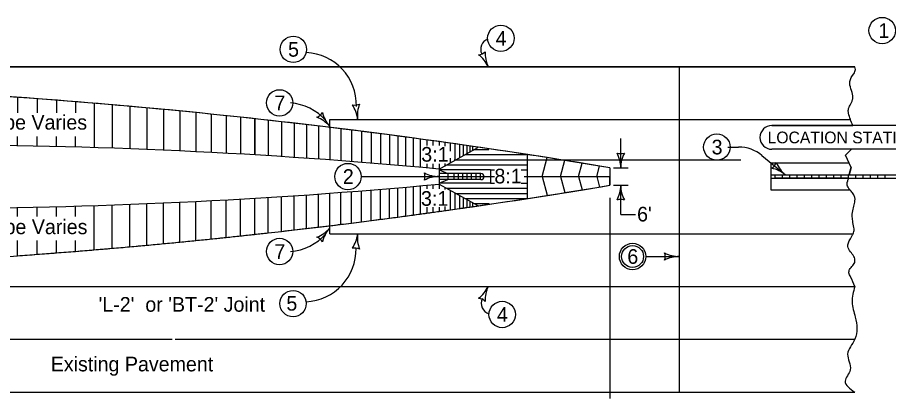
# Model space of a CAD drawing. Extents: x 10028 to 81668, y 3581 to 11018.
# Drawn here: x 14614 to 15802, y 4220 to 4740 of the extents above; entities that cross this region are included whole.
import ezdxf

# ---------------------------------------------------------------- set-up
doc = ezdxf.new("R2010")
doc.units = 0
for name, color, linetype in [('dsnCellsNorthArrow', 7, 'Continuous'), ('dsnStdLabel', 7, 'Continuous'), ('dsnStdShading', 7, 'Continuous'), ('dsnTextFinalPlan', 7, 'Continuous'), ('dsnTextTabulation', 7, 'Continuous'), ('Level 10', 7, 'Continuous'), ('Level 5', 7, 'Continuous'), ('Level 6', 7, 'Continuous'), ('SheetAddendum', 7, 'Continuous')]:
    doc.layers.add(name, color=color, linetype=linetype)

msp = doc.modelspace()

# ---------------------------------------------------------------- linework, layer by layer
at = {"layer": 'dsnCellsNorthArrow'}
for p, q in [((13916.5, 4301.1), (14824.8, 4301.1)), ((14828.9, 4301.1), (15755.5, 4301.1))]:
    msp.add_line(p, q, dxfattribs=at)
at = {"layer": 'dsnStdLabel'}
for p, q in [((15849.9, 4592.8), (15642.4, 4592.8)), ((15849.9, 4560.3), (15642.3, 4560.3))]:
    msp.add_line(p, q, dxfattribs=at)
msp.add_arc((15642.4, 4576.5), 16.2, 90, 270, dxfattribs=at)
at = {"layer": 'dsnStdShading'}
for p, q in [((15516.2, 4672.7), (13978.9, 4672.7)), ((15755.4, 4672.7), (15516.2, 4672.7)), ((14973.8, 4597.9), (14973.8, 4597.9)), ((15642.4, 4592.8), (15752.9, 4592.8)), ((15751.1, 4560.3), (15642.4, 4560.3)), ((15742.6, 4552.1), (15751.1, 4560.3)), ((15336.2, 4548.9), (15336.2, 4549)), ((15750.4, 4535.4), (15742.6, 4552.1)), ((15421.4, 4535.1), (15421.4, 4523.1)), ((15646.9, 4520.7), (15646.9, 4525.5)), ((15421.4, 4523.1), (15421.4, 4511.1)), ((15203.8, 4477.5), (15203.8, 4477.5)), ((15216.4, 4479.3), (15216.4, 4479.3)), ((15221.8, 4480.1), (15221.8, 4480.1)), ((15226.6, 4480.8), (15226.6, 4480.8)), ((15230.8, 4481.4), (15230.8, 4481.4)), ((15234.4, 4481.9), (15234.4, 4481.9)), ((15121, 4466.3), (15121, 4466.3)), ((15132.4, 4467.8), (15132.4, 4467.8)), ((15143.2, 4469.2), (15143.2, 4469.2)), ((15153.4, 4470.6), (15153.4, 4470.6)), ((15163, 4471.9), (15163, 4471.9)), ((15172, 4473.1), (15172, 4473.1)), ((15180.4, 4474.3), (15180.4, 4474.3)), ((15188.8, 4475.4), (15188.8, 4475.4)), ((15196.6, 4476.5), (15196.6, 4476.5)), ((15024.4, 4454.1), (15024.4, 4454.1)), ((15040, 4456), (15040, 4456)), ((15055, 4457.9), (15055, 4457.9)), ((15069.4, 4459.6), (15069.4, 4459.6)), ((15083.2, 4461.4), (15083.2, 4461.4)), ((15096.4, 4463.1), (15096.4, 4463.1)), ((15109, 4464.7), (15109, 4464.7)), ((14918.2, 4442.1), (14918.2, 4442.1)), ((14937.4, 4444.2), (14937.4, 4444.2)), ((14956, 4446.2), (14956, 4446.2)), ((14974, 4448.3), (14974, 4448.3)), ((14991.4, 4450.3), (14991.4, 4450.3)), ((15008.2, 4452.2), (15008.2, 4452.2)), ((14813.2, 4431.5), (14813.2, 4431.5)), ((14835.4, 4433.6), (14835.4, 4433.6)), ((14857, 4435.8), (14857, 4435.8)), ((14878, 4437.9), (14878, 4437.9)), ((14898.4, 4440), (14898.4, 4440)), ((14667.4, 4419), (14667.4, 4419)), ((14693.2, 4421), (14693.2, 4421)), ((14718.4, 4423.1), (14718.4, 4423.1)), ((14743, 4425.2), (14743, 4425.2)), ((14767, 4427.3), (14767, 4427.3)), ((14790.4, 4429.4), (14790.4, 4429.4)), ((14614, 4415), (14614, 4415)), ((14641, 4417), (14641, 4417)), ((13978, 4373.1), (15516.2, 4373.1)), ((15516.2, 4373.1), (15755.5, 4373.1))]:
    msp.add_line(p, q, dxfattribs=at)
for points in [[(14973.8, 4597.9), (14973.8, 4597.9)], [(15752.9, 4592.8), (15752.9, 4592.8)], [(15336.2, 4549), (15336.2, 4548.9)], [(15646.9, 4525.5), (15656.9, 4525.5), (15666.9, 4525.5), (15676.9, 4525.5), (15686.9, 4525.5), (15696.9, 4525.5), (15706.9, 4525.5), (15716.9, 4525.5), (15726.9, 4525.5), (15736.9, 4525.5), (15746.9, 4525.5), (15747.7, 4525.5)], [(15747.7, 4525.5), (15747.7, 4525.5)], [(15747.4, 4520.7), (15746.9, 4520.7), (15736.9, 4520.7), (15726.9, 4520.7), (15716.9, 4520.7), (15706.9, 4520.7), (15696.9, 4520.7), (15686.9, 4520.7), (15676.9, 4520.7), (15666.9, 4520.7), (15656.9, 4520.7), (15646.9, 4520.7)], [(15203.8, 4477.5), (15203.8, 4477.5)], [(15216.4, 4479.3), (15216.4, 4479.3)], [(15221.8, 4480.1), (15221.8, 4480.1)], [(15226.6, 4480.8), (15226.6, 4480.8)], [(15230.8, 4481.4), (15230.8, 4481.4)], [(15234.4, 4481.9), (15234.4, 4481.9)], [(15121, 4466.3), (15121, 4466.3)], [(15132.4, 4467.8), (15132.4, 4467.8)], [(15143.2, 4469.2), (15143.2, 4469.2)], [(15153.4, 4470.6), (15153.4, 4470.6)], [(15163, 4471.9), (15163, 4471.9)], [(15172, 4473.1), (15172, 4473.1)], [(15180.4, 4474.3), (15180.4, 4474.3)], [(15188.8, 4475.4), (15188.8, 4475.4)], [(15196.6, 4476.5), (15196.6, 4476.5)], [(15024.4, 4454.1), (15024.4, 4454.1)], [(15040, 4456), (15040, 4456)], [(15055, 4457.9), (15055, 4457.9)], [(15069.4, 4459.6), (15069.4, 4459.6)], [(15083.2, 4461.4), (15083.2, 4461.4)], [(15096.4, 4463.1), (15096.4, 4463.1)], [(15109, 4464.7), (15109, 4464.7)], [(14918.2, 4442.1), (14918.2, 4442.1)], [(14937.4, 4444.2), (14937.4, 4444.2)], [(14956, 4446.2), (14956, 4446.2)], [(14974, 4448.3), (14974, 4448.3)], [(14991.4, 4450.3), (14991.4, 4450.3)], [(15008.2, 4452.2), (15008.2, 4452.2)], [(14813.2, 4431.5), (14813.2, 4431.5)], [(14835.4, 4433.6), (14835.4, 4433.6)], [(14857, 4435.8), (14857, 4435.8)], [(14878, 4437.9), (14878, 4437.9)], [(14898.4, 4440), (14898.4, 4440)], [(14667.4, 4419), (14667.4, 4419)], [(14693.2, 4421), (14693.2, 4421)], [(14718.4, 4423.1), (14718.4, 4423.1)], [(14743, 4425.2), (14743, 4425.2)], [(14767, 4427.3), (14767, 4427.3)], [(14790.4, 4429.4), (14790.4, 4429.4)], [(14614, 4415), (14614, 4415)], [(14641, 4417), (14641, 4417)]]:
    msp.add_lwpolyline(points, dxfattribs=at)
for centre, radius, start, end in [((14003, -3944.1), 8597, 83.51664, 86.48991), ((14003, -3944.1), 8597, 81.07917, 83.51663), ((15642.4, 4576.5), 16.2, 90, 270), ((14003, -3944.1), 8597, 80.50385, 81.07911), ((14003.1, 12988.9), 8595.6, 278.23561, 279.49716), ((14003.1, 12988.9), 8595.6, 277.9811, 278.02957), ((14003.1, 12988.9), 8595.6, 278.02957, 278.11439), ((14003.1, 12988.9), 8595.6, 278.11439, 278.15075), ((14003.1, 12988.9), 8595.6, 278.15075, 278.18308), ((14003.1, 12988.9), 8595.6, 278.18308, 278.21136), ((14003.1, 12988.9), 8595.6, 278.21136, 278.23561), ((14003.1, 12988.9), 8595.6, 277.39189, 277.47256), ((14003.1, 12988.9), 8595.6, 277.47256, 277.5492), ((14003.1, 12988.9), 8595.6, 277.5492, 277.62183), ((14003.1, 12988.9), 8595.6, 277.62183, 277.69043), ((14003.1, 12988.9), 8595.6, 277.69043, 277.755), ((14003.1, 12988.9), 8595.6, 277.75501, 277.81555), ((14003.1, 12988.9), 8595.6, 277.81555, 277.87207), ((14003.1, 12988.9), 8595.6, 277.87208, 277.9286), ((14003.1, 12988.9), 8595.6, 277.9286, 277.9811), ((14003.1, 12988.9), 8595.6, 276.71486, 276.8236), ((14003.1, 12988.9), 8595.6, 276.8236, 276.92834), ((14003.1, 12988.9), 8595.6, 276.92834, 277.02907), ((14003.1, 12988.9), 8595.6, 277.02907, 277.1258), ((14003.1, 12988.9), 8595.6, 277.1258, 277.21851), ((14003.1, 12988.9), 8595.6, 277.21851, 277.30721), ((14003.1, 12988.9), 8595.6, 277.30721, 277.39189), ((14003.1, 12988.9), 8595.6, 275.97845, 276.11117), ((14003.1, 12988.9), 8595.6, 276.11117, 276.2399), ((14003.1, 12988.9), 8595.6, 276.2399, 276.36463), ((14003.1, 12988.9), 8595.6, 276.36463, 276.48537), ((14003.1, 12988.9), 8595.6, 276.48537, 276.60212), ((14003.1, 12988.9), 8595.6, 276.60212, 276.71486), ((14003.1, 12988.9), 8595.6, 275.25508, 275.40772), ((14003.1, 12988.9), 8595.6, 275.40772, 275.55638), ((14003.1, 12988.9), 8595.6, 275.55638, 275.70105), ((14003.1, 12988.9), 8595.6, 275.70105, 275.84175), ((14003.1, 12988.9), 8595.6, 275.84175, 275.97845), ((14003.1, 12988.9), 8595.6, 274.25578, 274.43226), ((14003.1, 12988.9), 8595.6, 274.43226, 274.60477), ((14003.1, 12988.9), 8595.6, 274.60477, 274.77331), ((14003.1, 12988.9), 8595.6, 274.77331, 274.93787), ((14003.1, 12988.9), 8595.6, 274.93787, 275.09846), ((14003.1, 12988.9), 8595.6, 275.09846, 275.25508), ((14003.1, 12988.9), 8595.6, 274.07532, 274.25577)]:
    msp.add_arc(centre, radius, start, end, dxfattribs=at)
for points in [[(15752.9, 4592.8), (15747, 4609.4), (15746.7, 4614.6), (15749, 4620.4), (15752.5, 4628.1), (15752.7, 4633), (15750.2, 4642.8), (15748.7, 4652.9), (15754, 4663.3), (15756.3, 4669.3), (15755.4, 4672.7)], [(15755.5, 4373.1), (15749.7, 4386.1), (15747.4, 4391.6), (15748.4, 4396.3), (15752.6, 4401.9), (15755.7, 4407.5), (15754.1, 4414), (15749.6, 4420.5), (15745.9, 4427.8), (15746.8, 4432.5), (15752.4, 4443.6), (15754.5, 4449.4), (15754.1, 4453.7), (15752.6, 4462.7), (15752, 4469.7), (15752.3, 4474), (15754.3, 4482.8), (15755.7, 4490), (15755.5, 4494.4), (15753.2, 4499.4), (15749.3, 4504.3), (15745.5, 4509.9), (15744.9, 4513.1), (15745.8, 4517.2), (15747.4, 4520.7)]]:
    msp.add_spline(points, degree=3, dxfattribs=at)
msp.add_open_spline([(15747.7, 4525.5), (15748.6, 4528.8), (15749.5, 4532.1), (15750.4, 4535.4)], degree=2, dxfattribs=at)
at = {"layer": 'dsnTextFinalPlan'}
for p, q in [((15436.4, 4535.1), (15436.4, 4575.1)), ((15582.4, 4563.3), (15597.1, 4563.3)), ((15628.9, 4551.8), (15660.8, 4525.5)), ((15082.6, 4523.1), (15188.7, 4523.1)), ((15436.4, 4471.1), (15436.4, 4511.1)), ((15421.4, 4494.2), (15421.4, 4220.2)), ((15436.4, 4471.1), (15456.4, 4471.1)), ((15470.5, 4414), (15516.2, 4414))]:
    msp.add_line(p, q, dxfattribs=at)
for centre, radius, start, end in [((15260.5, 4696.7), 15, 111.3824, 205.2927), ((15004.6, 4620.7), 71.5, 358.5257, 87.654), ((15240.7, 4705.5), 16.4, 276.8646, 312.3313), ((15294.2, 4690.8), 42.5, 176.5254, 204.5979), ((15216.9, 4655.4), 42.5, 24.5979, 52.6704), ((14981.4, 4553.6), 70, 40.9906, 85.9043), ((15073.7, 4637), 16.4, 258.6446, 294.1113), ((15035.5, 4596.8), 42.5, 6.3779, 34.4504), ((15119.9, 4606.3), 42.5, 158.3054, 186.3779), ((15015.8, 4619), 16.4, 293.2594, 328.7261), ((15071.2, 4620), 42.5, 192.9203, 220.9928), ((15007.1, 4564.2), 42.5, 40.9928, 69.0653), ((15597.1, 4513.3), 50, 50.4322, 90), ((15436.4, 4570.7), 16.4, 252.2666, 287.7333), ((15393.9, 4535.1), 42.5, 0, 28.0725), ((15478.9, 4535.1), 42.5, 151.9275, 180), ((15633.3, 4548.2), 16.4, 302.6988, 338.1655), ((15687.9, 4558.2), 42.5, 202.3597, 230.4322), ((15153.1, 4523.1), 16.4, 342.2666, 17.7333), ((15188.7, 4565.6), 42.5, 241.9275, 270), ((15633.7, 4492.7), 42.5, 50.4322, 78.5047), ((15188.7, 4480.6), 42.5, 90, 118.0725), ((15393.9, 4511.1), 42.5, 331.9275, 0), ((15478.9, 4511.1), 42.5, 180, 208.0725), ((15436.4, 4475.4), 16.4, 72.2666, 107.7334), ((14981.4, 4490.8), 70, 274.0957, 319.0094), ((15007.1, 4480.2), 42.5, 290.9347, 319.0072), ((15071.2, 4424.4), 42.5, 139.0072, 167.0797), ((15035.5, 4449.3), 42.5, 325.5496, 353.6221), ((15119.9, 4439.9), 42.5, 173.6221, 201.6946), ((15015.8, 4425.4), 16.4, 31.2739, 66.7406), ((15004.1, 4423.7), 71.5, 272.6651, 1.4743), ((15073.7, 4409.2), 16.4, 65.8887, 101.3554), ((15480.6, 4414), 16.4, 342.2666, 17.7333), ((15516.2, 4456.5), 42.5, 241.9275, 270), ((15516.2, 4371.5), 42.5, 90, 118.0725), ((15216.9, 4390.8), 42.5, 307.3296, 335.4021), ((15294.2, 4355.4), 42.5, 155.4021, 183.4746), ((15240.7, 4340.7), 16.4, 47.6687, 83.1354), ((15261.3, 4350.2), 15, 154.7073, 252.9017)]:
    msp.add_arc(centre, radius, start, end, dxfattribs=at)
at = {"layer": 'dsnTextTabulation'}
msp.add_line((15209.2, 4546), (15600.1, 4546), dxfattribs=at)
msp.add_circle((15452.5, 4414), 15, dxfattribs=at)
at = {"layer": 'Level 10'}
for centre in [(15792.8, 4722.2), (15273, 4711.7), (14990.1, 4696.6), (14971.4, 4623.6), (15567.4, 4563.3), (15064.6, 4523.1), (14971.4, 4420.8), (15452.5, 4414), (14989.7, 4349.7), (15274.8, 4334.9)]:
    msp.add_circle(centre, 18, dxfattribs=at)
at = {"layer": 'Level 5'}
msp.add_arc((15245.7, 4523.1), 4.2, 270, 90, dxfattribs=at)
at = {"layer": 'SheetAddendum'}
for p, q in [((13978.9, 4672.7), (15516.2, 4672.7)), ((15516.2, 4672.7), (15516.2, 4601.1)), ((15516.2, 4672.7), (15755.4, 4672.7)), ((14614, 4631.1), (14614, 4610.2)), ((14641, 4629.2), (14641, 4610.2)), ((14667.4, 4627.2), (14667.4, 4610.2)), ((14693.2, 4625.1), (14693.2, 4610.2)), ((14718.4, 4623.1), (14718.4, 4562.5)), ((14743, 4621), (14743, 4561.7)), ((14767, 4618.9), (14767, 4560.9)), ((14790.4, 4616.7), (14790.4, 4560)), ((14813.2, 4614.6), (14813.2, 4559)), ((14835.4, 4612.5), (14835.4, 4558)), ((14857, 4610.4), (14857, 4557)), ((14878, 4608.2), (14878, 4555.9)), ((14898.4, 4606.1), (14898.4, 4554.8)), ((14918.2, 4604), (14918.2, 4553.7)), ((14937.4, 4601.9), (14937.4, 4552.6)), ((14937.4, 4552.6), (14937.4, 4601.9)), ((14956, 4599.9), (14956, 4551.4)), ((14973.8, 4597.9), (14973.8, 4550.3)), ((14991.4, 4595.9), (14991.4, 4549.1)), ((15040, 4589.1), (15040, 4601.1)), ((15040, 4601.1), (15750, 4601.1)), ((15516.2, 4601.1), (15516.2, 4373.1)), ((15008.2, 4593.9), (15008.2, 4548)), ((15024.4, 4592), (15024.4, 4546.8)), ((15040, 4589.1), (15040, 4545.7)), ((15055, 4588.3), (15055, 4544.6)), ((15069.4, 4586.5), (15069.4, 4543.5)), ((15083.2, 4584.7), (15083.2, 4542.4)), ((14614, 4565.1), (14614, 4577.6)), ((14641, 4564.6), (14641, 4577.6)), ((14667.4, 4564), (14667.4, 4577.6)), ((14693.2, 4563.3), (14693.2, 4577.6)), ((15096.4, 4583.1), (15096.4, 4541.4)), ((15109, 4581.4), (15109, 4540.3)), ((15121, 4579.9), (15121, 4539.3)), ((15132.4, 4578.4), (15132.4, 4538.4)), ((15143.2, 4576.9), (15143.2, 4537.4)), ((15153.4, 4575.6), (15153.4, 4536.5)), ((15163, 4574.3), (15163, 4535.7)), ((15172, 4573), (15172, 4565.3)), ((15180.4, 4571.9), (15180.4, 4565.3)), ((15188.8, 4570.7), (15188.8, 4565.3)), ((15188.8, 4533.3), (15241.4, 4562.7)), ((15196.6, 4569.6), (15196.6, 4564.5)), ((15203.8, 4568.6), (15203.8, 4557.5)), ((15210.4, 4567.7), (15210.4, 4545.4)), ((15216.4, 4566.8), (15216.4, 4548.7)), ((15221.8, 4566), (15221.8, 4551.7)), ((15226.6, 4565.4), (15226.6, 4554.4)), ((15230.8, 4564.8), (15230.8, 4556.8)), ((15234.4, 4564.2), (15234.4, 4558.8)), ((15742.6, 4552.1), (15751.1, 4560.3)), ((15224.1, 4553), (15307.3, 4553)), ((15236.7, 4560), (15256.5, 4560)), ((15308.7, 4552.8), (15308.7, 4493.3)), ((15329.3, 4523.1), (15336.2, 4549)), ((15750.4, 4535.3), (15742.6, 4552.1)), ((15172, 4540.3), (15172, 4534.9)), ((15180.4, 4540.3), (15180.4, 4534.1)), ((15180.4, 4539.6), (15180.4, 4538.4)), ((15188.8, 4540.3), (15188.8, 4506.3)), ((15196.6, 4541.1), (15196.6, 4537.6)), ((15199.2, 4539.1), (15308.7, 4539.1)), ((15203.8, 4548.2), (15203.8, 4541.7)), ((15211.6, 4546.1), (15308.7, 4546.1)), ((15354.1, 4523.1), (15360.1, 4545.5)), ((15379, 4523.1), (15383.8, 4541.2)), ((15403.8, 4523.1), (15407.6, 4537.3)), ((15641, 4541.9), (15641, 4505.1)), ((15641, 4541.9), (15747.5, 4541.9)), ((15188.7, 4533.3), (15188.7, 4512.8)), ((15258.9, 4532.1), (15188.7, 4532.1)), ((15188.7, 4532.1), (15200.7, 4527.3)), ((15200.7, 4527.3), (15188.7, 4527.3)), ((15245.7, 4527.3), (15200.7, 4527.3)), ((15200.7, 4527.3), (15200.7, 4518.9)), ((15208.7, 4527.3), (15208.7, 4518.9)), ((15214.7, 4527.3), (15214.7, 4518.9)), ((15220.7, 4527.3), (15220.7, 4518.9)), ((15226.7, 4527.3), (15226.7, 4518.9)), ((15232.7, 4527.3), (15232.7, 4518.9)), ((15238.7, 4527.3), (15238.7, 4518.9)), ((15244.7, 4527.3), (15244.7, 4518.9)), ((15258.9, 4532.1), (15258.9, 4514.1)), ((15258.9, 4532.1), (15264.5, 4532.1)), ((15300.7, 4532.1), (15308.7, 4532.1)), ((15421.4, 4535.1), (15421.4, 4523.1)), ((15421.4, 4535.1), (15421.4, 4511.1)), ((15426.4, 4535.1), (15446.4, 4535.1)), ((15641.2, 4525.5), (15969.2, 4525.5)), ((15646.9, 4520.7), (15646.9, 4525.5)), ((15656.9, 4520.7), (15656.9, 4525.5)), ((15666.9, 4520.7), (15666.9, 4525.5)), ((15676.9, 4520.7), (15676.9, 4525.5)), ((15686.9, 4520.7), (15686.9, 4525.5)), ((15696.9, 4520.7), (15696.9, 4525.5)), ((15706.9, 4520.7), (15706.9, 4525.5)), ((15716.9, 4520.7), (15716.9, 4525.5)), ((15726.9, 4520.7), (15726.9, 4525.5)), ((15736.9, 4520.7), (15736.9, 4525.5)), ((15746.9, 4520.7), (15746.9, 4525.5)), ((15750.4, 4535.4), (15747.7, 4525.5)), ((15756.9, 4520.7), (15756.9, 4525.5)), ((15766.9, 4520.7), (15766.9, 4525.5)), ((15776.9, 4520.7), (15776.9, 4525.5)), ((15786.9, 4520.7), (15786.9, 4525.5)), ((15796.9, 4520.7), (15796.9, 4525.5)), ((15188.7, 4523.1), (15264.5, 4523.1)), ((15188.7, 4514.1), (15200.7, 4518.9)), ((15200.7, 4518.9), (15188.7, 4518.9)), ((15258.9, 4514.1), (15188.7, 4514.1)), ((15188.8, 4512.8), (15241.5, 4483.4)), ((15245.7, 4518.9), (15200.7, 4518.9)), ((15258.9, 4514.1), (15264.5, 4514.1)), ((15300.8, 4514.1), (15308.7, 4514.1)), ((15304.6, 4523.1), (15421.4, 4523.1)), ((15329.3, 4523.1), (15336.1, 4497.5)), ((15354.1, 4523.1), (15360, 4501.2)), ((15379, 4523.1), (15383.8, 4505)), ((15403.8, 4523.1), (15407.6, 4508.8)), ((15421.4, 4511.1), (15421.4, 4523.1)), ((15641.2, 4520.7), (15967.4, 4520.7)), ((15055, 4457.9), (15055, 4501.5)), ((15069.4, 4459.6), (15069.4, 4502.6)), ((15083.2, 4461.4), (15083.2, 4503.7)), ((15096.4, 4463.1), (15096.4, 4504.8)), ((15109, 4464.7), (15109, 4505.8)), ((15121, 4466.3), (15121, 4506.8)), ((15132.4, 4467.8), (15132.4, 4507.8)), ((15143.2, 4508.7), (15143.2, 4469.2)), ((15153.4, 4509.6), (15153.4, 4470.6)), ((15163, 4510.5), (15163, 4471.9)), ((15172, 4511.3), (15172, 4506.3)), ((15180.4, 4512), (15180.4, 4506.3)), ((15196.6, 4508.5), (15196.6, 4505.4)), ((15199.1, 4507.1), (15308.7, 4507.1)), ((15203.8, 4504.5), (15203.8, 4477.5)), ((15210.4, 4500.8), (15210.4, 4479)), ((15426.4, 4511.1), (15446.4, 4511.1)), ((15641, 4505.1), (15749.5, 4505.1)), ((14857, 4435.8), (14857, 4489.2)), ((14878, 4437.9), (14878, 4490.2)), ((14898.4, 4440), (14898.4, 4491.3)), ((14918.2, 4442.1), (14918.2, 4492.4)), ((14937.4, 4444.2), (14937.4, 4493.6)), ((14956, 4446.2), (14956, 4494.7)), ((14974, 4448.3), (14974, 4495.9)), ((14991.4, 4450.3), (14991.4, 4497)), ((15008.2, 4452.2), (15008.2, 4498.1)), ((15024.4, 4454.1), (15024.4, 4499.3)), ((15040, 4456), (15040, 4500.4)), ((15211.6, 4500.1), (15308.7, 4500.1)), ((15216.4, 4497.5), (15216.4, 4479.3)), ((15221.8, 4494.4), (15221.8, 4480.1)), ((15224.1, 4493.2), (15307.8, 4493.2)), ((15226.6, 4491.8), (15226.6, 4480.8)), ((15230.8, 4489.4), (15230.8, 4481.4)), ((14614, 4468.6), (14614, 4481)), ((14641, 4468.6), (14641, 4481.6)), ((14667.4, 4468.6), (14667.4, 4482.2)), ((14693.2, 4468.6), (14693.2, 4482.8)), ((14718.4, 4423.1), (14718.4, 4483.6)), ((14743, 4425.2), (14743, 4484.4)), ((14767, 4427.3), (14767, 4485.3)), ((14790.4, 4429.4), (14790.4, 4486.2)), ((14813.2, 4431.5), (14813.2, 4487.1)), ((14835.4, 4433.6), (14835.4, 4488.1)), ((15172, 4481.3), (15172, 4473.1)), ((15180.4, 4481.3), (15180.4, 4474.3)), ((15188.8, 4481.3), (15188.8, 4475.4)), ((15196.6, 4482.1), (15196.6, 4476.5)), ((15234.4, 4487.4), (15234.4, 4481.9)), ((15236.7, 4486.2), (15257, 4486.2)), ((15040, 4445.1), (15040, 4457.1)), ((15040, 4445.1), (15753, 4445.1)), ((14614, 4415), (14614, 4435.9)), ((14641, 4417), (14641, 4435.9)), ((14667.4, 4419), (14667.4, 4435.9)), ((14693.2, 4421), (14693.2, 4435.9)), ((13978, 4373.1), (15516.2, 4373.1)), ((15516.2, 4373.1), (15516.2, 4229.1)), ((15516.2, 4373.1), (15755.5, 4373.1)), ((13916.5, 4229.1), (15755.5, 4229.1))]:
    msp.add_line(p, q, dxfattribs=at)
for centre, radius, start, end in [((14003, -3944.1), 8597, 80.50385, 86.52493), ((14480.2, -3067), 7633.3, 84.67428, 90), ((14480.2, 12113.1), 7633.3, 270, 275.32661), ((14003.1, 12988.9), 8595.6, 273.47608, 279.49716)]:
    msp.add_arc(centre, radius, start, end, dxfattribs=at)
for points in [[(15752.9, 4592.8), (15747, 4609.4), (15746.7, 4614.6), (15749, 4620.4), (15752.5, 4628.1), (15752.7, 4633), (15750.2, 4642.8), (15748.7, 4652.9), (15754, 4663.3), (15756.3, 4669.3), (15755.4, 4672.7)], [(15755.5, 4373.1), (15749.7, 4386.1), (15747.4, 4391.6), (15748.4, 4396.3), (15752.6, 4401.9), (15755.7, 4407.5), (15754.1, 4414), (15749.6, 4420.5), (15745.9, 4427.8), (15746.8, 4432.5), (15752.4, 4443.6), (15754.5, 4449.4), (15754.1, 4453.7), (15752.6, 4462.7), (15752, 4469.7), (15752.3, 4474), (15754.3, 4482.8), (15755.7, 4490), (15755.5, 4494.4), (15753.2, 4499.4), (15749.3, 4504.3), (15745.5, 4509.9), (15744.9, 4513.1), (15745.8, 4517.2), (15747.4, 4520.7)], [(15755.5, 4373.1), (15751.7, 4351.9), (15756, 4331.3), (15755.5, 4301.1), (15745.7, 4280.8), (15749.2, 4259.4), (15742.3, 4244), (15755.5, 4229.1)]]:
    msp.add_spline(points, degree=3, dxfattribs=at)

# ---------------------------------------------------------------- texts
at = {"layer": 'dsnStdLabel'}
msp.add_text('LOCATION STATION', height=16, dxfattribs=at).set_placement((15636.6, 4568.4))
at = {"layer": 'Level 6'}
for s, p in [('1', (15787.6, 4712.2)), ('4', (15265.9, 4701.7)), ('5', (14982.9, 4686.6)), ('7', (14964.3, 4613.6)), ('Slope Varies', (14557.3, 4587.1)), ('3', (15560.3, 4553.3)), ('3:1', (15164.5, 4543.4)), ('2', (15057.6, 4513.1)), ('8:1', (15264.2, 4513.7)), ('3:1', (15164.1, 4483.2)), ("6'", (15458.7, 4461.8)), ('Slope Varies', (14557.8, 4444.5)), ('7', (14964.3, 4410.8)), ('6', (15445.4, 4404)), ("'L-2'  or 'BT-2' Joint", (14724.6, 4338.7)), ('5', (14980.6, 4340.2)), ('4', (15267.7, 4324.9)), ('Existing Pavement', (14659.4, 4257.3))]:
    msp.add_text(s, height=20, dxfattribs=at).set_placement(p)

doc.saveas('drawing.dxf')
